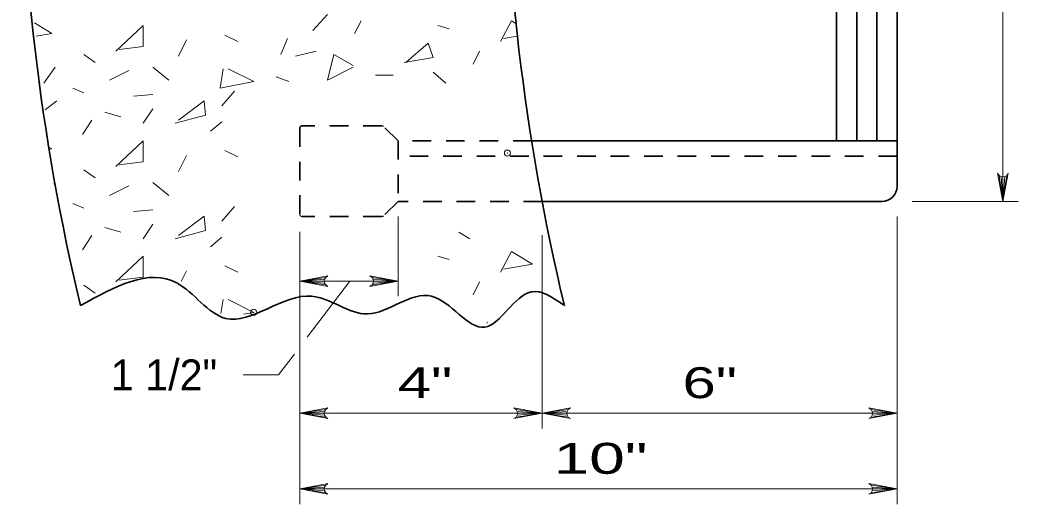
# Model space of a CAD drawing. Extents: x 16 to 133, y -56 to 112.
# Drawn here: x 22.21 to 55.21, y 65.71 to 81.71 of the extents above; entities that cross this region are included whole.
import ezdxf
from ezdxf.enums import TextEntityAlignment as Align

# ---------------------------------------------------------------- set-up
doc = ezdxf.new("R2010")
doc.units = 0
doc.header["$LTSCALE"] = 0.41
doc.header["$PDMODE"] = 32
doc.header["$PDSIZE"] = 0.205
doc.linetypes.add('SHORT_DASHED', pattern=[2.7, 1.5, -1.2])
for name, color, linetype, lineweight in [('1', 7, 'Continuous', 35), ('10', 7, 'Continuous', 13), ('13', 7, 'Continuous', 25), ('6', 7, 'Continuous', 13)]:
    doc.layers.add(name, color=color, linetype=linetype, lineweight=lineweight)

msp = doc.modelspace()

# ---------------------------------------------------------------- linework, layer by layer
at = {"layer": '1'}
for p, q in [((51.2132, 76.2094), (51.2132, 103.2094)), ((49.2132, 77.7094), (49.2132, 101.7094)), ((49.8798, 77.7094), (49.8798, 101.7094)), ((50.5465, 77.7094), (50.5465, 101.7094)), ((51.2132, 77.7094), (39.1307, 77.7094)), ((50.7132, 75.7094), (39.4787, 75.7094))]:
    msp.add_line(p, q, dxfattribs=at)
at = {"layer": '1', "linetype": 'SHORT_DASHED'}
for p, q in [((31.4632, 78.126), (31.4632, 75.2927)), ((34.1786, 78.2094), (31.5465, 78.2094)), ((34.7132, 77.7094), (34.2376, 78.185)), ((34.7132, 77.7094), (34.7132, 75.7094)), ((39.1307, 77.7094), (34.7132, 77.7094)), ((51.2132, 77.2094), (34.7132, 77.2094)), ((34.7132, 75.7094), (34.2376, 75.2338)), ((39.4787, 75.7094), (34.7132, 75.7094)), ((34.1786, 75.2094), (31.5465, 75.2094))]:
    msp.add_line(p, q, dxfattribs=at)
at = {"layer": '1'}
for centre, radius, start, end in [((95.4632, 89.267), 73.25, 166.58032, 193.41967), ((111.4632, 89.267), 73.25, 166.58032, 193.41967), ((50.7132, 76.2094), 0.5, 270, 0)]:
    msp.add_arc(centre, radius, start, end, dxfattribs=at)
at = {"layer": '1', "linetype": 'SHORT_DASHED'}
msp.add_arc((31.5465, 78.126), 0.0833, 90, 180, dxfattribs=at)
at = {"layer": '1'}
msp.add_spline([(24.2131, 72.267), (27.3964, 73.0185), (29.0086, 71.8453), (31.8666, 72.5785), (33.6986, 71.9919), (35.8238, 72.5785), (37.5826, 71.552), (39.1216, 72.7252), (40.2131, 72.267)], degree=3, dxfattribs=at)
at = {"layer": '10'}
for p, q in [((54.7132, 75.7094), (54.7132, 103.7094)), ((51.7132, 75.7094), (55.2132, 75.7094)), ((34.7132, 75.2094), (34.7132, 72.5756)), ((51.2132, 75.2094), (51.2132, 65.7094)), ((31.4632, 74.7094), (31.4632, 65.7094)), ((39.4787, 74.599), (39.4787, 68.2094)), ((34.7132, 73.0756), (31.4632, 73.0756)), ((31.7107, 71.222), (33.1186, 73.0756)), ((51.2132, 68.7094), (31.4632, 68.7094)), ((51.2132, 66.2094), (31.4632, 66.2094))]:
    msp.add_line(p, q, dxfattribs=at)
for points in [[(54.7132, 75.7094), (54.5384, 76.6414), (54.5882, 76.5696), (54.6507, 76.5326), (54.7132, 76.5219), (54.7757, 76.5326), (54.8382, 76.5696), (54.8879, 76.6414), (54.7132, 75.7094), (54.8382, 76.5696), (54.7757, 76.5326), (54.7132, 75.7094), (54.7132, 76.5219), (54.6507, 76.5326), (54.7132, 75.7094), (54.5882, 76.5696)], [(31.4632, 73.0756), (32.3952, 73.2503), (32.3234, 73.2006), (32.2864, 73.1381), (32.2757, 73.0756), (32.2864, 73.0131), (32.3234, 72.9506), (32.3952, 72.9008), (31.4632, 73.0756), (32.3234, 72.9506), (32.2864, 73.0131), (31.4632, 73.0756), (32.2757, 73.0756), (32.2864, 73.1381), (31.4632, 73.0756), (32.3234, 73.2006)], [(34.7132, 73.0756), (33.7811, 72.9008), (33.8529, 72.9506), (33.89, 73.0131), (33.9007, 73.0756), (33.89, 73.1381), (33.8529, 73.2006), (33.7811, 73.2503), (34.7132, 73.0756), (33.8529, 73.2006), (33.89, 73.1381), (34.7132, 73.0756), (33.9007, 73.0756), (33.89, 73.0131), (34.7132, 73.0756), (33.8529, 72.9506)], [(29.588, 69.9768), (30.7649, 69.9768), (31.287, 70.6642)], [(31.4632, 68.7094), (32.3952, 68.8841), (32.3234, 68.8344), (32.2864, 68.7719), (32.2757, 68.7094), (32.2864, 68.6469), (32.3234, 68.5844), (32.3952, 68.5346), (31.4632, 68.7094), (32.3234, 68.5844), (32.2864, 68.6469), (31.4632, 68.7094), (32.2757, 68.7094), (32.2864, 68.7719), (31.4632, 68.7094), (32.3234, 68.8344)], [(39.4787, 68.7094), (38.5467, 68.5346), (38.6185, 68.5844), (38.6555, 68.6469), (38.6662, 68.7094), (38.6555, 68.7719), (38.6185, 68.8344), (38.5467, 68.8841), (39.4787, 68.7094), (38.6185, 68.8344), (38.6555, 68.7719), (39.4787, 68.7094), (38.6662, 68.7094), (38.6555, 68.6469), (39.4787, 68.7094), (38.6185, 68.5844)], [(39.4787, 68.7094), (40.4108, 68.5346), (40.339, 68.5844), (40.302, 68.6469), (40.2912, 68.7094), (40.302, 68.7719), (40.339, 68.8344), (40.4108, 68.8841), (39.4787, 68.7094), (40.339, 68.8344), (40.302, 68.7719), (39.4787, 68.7094), (40.2912, 68.7094), (40.302, 68.6469), (39.4787, 68.7094), (40.339, 68.5844)], [(51.2132, 68.7094), (50.2811, 68.5346), (50.3529, 68.5844), (50.39, 68.6469), (50.4007, 68.7094), (50.39, 68.7719), (50.3529, 68.8344), (50.2811, 68.8841), (51.2132, 68.7094), (50.3529, 68.8344), (50.39, 68.7719), (51.2132, 68.7094), (50.4007, 68.7094), (50.39, 68.6469), (51.2132, 68.7094), (50.3529, 68.5844)], [(31.4632, 66.2094), (32.3952, 66.3841), (32.3234, 66.3344), (32.2864, 66.2719), (32.2757, 66.2094), (32.2864, 66.1469), (32.3234, 66.0844), (32.3952, 66.0346), (31.4632, 66.2094), (32.3234, 66.0844), (32.2864, 66.1469), (31.4632, 66.2094), (32.2757, 66.2094), (32.2864, 66.2719), (31.4632, 66.2094), (32.3234, 66.3344)], [(51.2132, 66.2094), (50.2811, 66.0346), (50.3529, 66.0844), (50.39, 66.1469), (50.4007, 66.2094), (50.39, 66.2719), (50.3529, 66.3344), (50.2811, 66.3841), (51.2132, 66.2094), (50.3529, 66.3344), (50.39, 66.2719), (51.2132, 66.2094), (50.4007, 66.2094), (50.39, 66.1469), (51.2132, 66.2094), (50.3529, 66.0844)]]:
    msp.add_lwpolyline(points, dxfattribs=at)
at = {"layer": '6'}
for p, q in [((32.3776, 81.8925), (31.901, 81.363)), ((33.4895, 81.6807), (33.2777, 81.2571)), ((36.0312, 81.5219), (36.4019, 81.416)), ((28.9887, 81.2042), (29.4123, 80.9924)), ((27.4531, 80.5158), (27.7178, 81.0453)), ((31.0538, 81.0983), (30.842, 80.5687)), ((38.6508, 81.173), (38.2022, 81.0983)), ((24.329, 80.5687), (24.6996, 80.304)), ((32.0069, 80.6747), (31.3185, 80.5158)), ((37.1961, 80.251), (37.4079, 80.6747)), ((23.3758, 80.1451), (23.0052, 79.6156)), ((25.8116, 80.0392), (25.1762, 79.7215)), ((26.6059, 80.1451), (27.1354, 79.7215)), ((33.9661, 79.8804), (34.5486, 79.8804)), ((35.8724, 79.9863), (36.296, 79.6156)), ((30.6831, 79.8274), (31.1067, 79.6686)), ((23.9583, 79.4568), (24.329, 79.2979)), ((25.9704, 79.192), (26.6059, 79.245)), ((28.8828, 78.8743), (29.3064, 79.3509)), ((23.4288, 79.0332), (23.0415, 78.7319)), ((25.0173, 78.6625), (25.5468, 78.5036)), ((26.2881, 78.2918), (26.6059, 78.7684)), ((24.5937, 78.3977), (24.276, 77.9212)), ((28.5121, 78.0271), (28.8828, 78.3448)), ((27.4531, 76.7033), (27.7178, 77.2328)), ((28.9887, 77.3917), (29.4123, 77.1799)), ((38.3313, 77.3073), (38.3313, 77.3073)), ((24.329, 76.7562), (24.6996, 76.4915)), ((23.3758, 76.3326), (23.3382, 76.2788)), ((26.6059, 76.3326), (27.1354, 75.909)), ((25.8116, 76.2267), (25.1762, 75.909)), ((23.9583, 75.6443), (24.329, 75.4854)), ((25.9704, 75.3795), (26.6059, 75.4325)), ((28.8828, 75.0618), (29.3064, 75.5384)), ((26.2881, 74.4793), (26.6059, 74.9559)), ((24.5937, 74.5852), (24.276, 74.1087)), ((25.0173, 74.85), (25.5468, 74.6911)), ((36.7196, 74.6911), (37.0902, 74.4793)), ((28.5121, 74.2146), (28.8828, 74.5323)), ((36.0312, 73.8969), (36.4019, 73.791)), ((27.5396, 73.0639), (27.7178, 73.4203)), ((28.9887, 73.5792), (29.4123, 73.3674)), ((24.329, 72.9437), (24.6996, 72.679)), ((37.1961, 72.626), (37.4079, 73.0497)), ((28.9357, 72.4672), (28.859, 72.007)), ((29.9411, 72.0439), (29.0946, 72.4672)), ((37.6487, 71.6839), (37.6727, 71.7259))]:
    msp.add_line(p, q, dxfattribs=at)
for points in [[(22.6992, 81.6083), (23.2699, 81.2571), (22.7513, 81.1707)], [(25.4939, 80.7276), (26.2881, 80.8335), (26.2881, 81.5219), (25.388, 80.6747)], [(38.0963, 80.9924), (38.467, 81.6807), (38.6137, 81.5904)], [(34.9192, 80.304), (35.8724, 80.4628), (35.7135, 80.9394), (34.9722, 80.304)], [(33.2248, 80.1451), (32.3776, 79.7215), (32.5894, 80.5687), (33.2248, 80.1981)], [(28.9357, 80.0922), (28.8298, 79.4568), (29.9418, 79.6686), (29.0946, 80.0922)], [(27.3472, 78.2918), (28.3532, 78.5566), (28.3003, 79.0332), (27.4531, 78.3977)], [(25.4939, 76.9151), (26.2881, 77.021), (26.2881, 77.7094), (25.388, 76.8622)], [(23.1887, 77.4946), (23.2699, 77.4446), (23.1961, 77.4323)], [(27.3472, 74.4793), (28.3532, 74.7441), (28.3003, 75.2207), (27.4531, 74.5852)], [(38.0963, 73.3674), (38.467, 74.0557), (39.1553, 73.6321), (38.2022, 73.4733)], [(25.4939, 73.1026), (26.2881, 73.2085), (26.2881, 73.8969), (25.388, 73.0497)], [(29.6119, 71.9807), (29.6119, 71.9807), (29.9389, 72.043)]]:
    msp.add_lwpolyline(points, dxfattribs=at)
at = {"layer": '6', "linetype": 'SHORT_DASHED'}
for centre, start, end in [((34.1787, 78.126), 45, 90), ((31.5465, 75.2927), 180, 270), ((34.1787, 75.2927), 270, 315)]:
    msp.add_arc(centre, 0.0833, start, end, dxfattribs=at)
at = {"layer": '6'}
for p in [(38.3313, 77.3073), (29.9389, 72.043)]:
    msp.add_point(p, dxfattribs=at)

# ---------------------------------------------------------------- texts
at = {"layer": '13'}
msp.add_text('1 1/2"', height=1.02, dxfattribs=at).set_placement((26.9751, 69.4668), align=Align.CENTER)
for s, width, p in [('4"', 1.45, (35.6059, 69.2094)), ('6"', 1.45, (45.0207, 69.2094)), ('10"', 1.55, (41.4098, 66.7094))]:
    msp.add_text(s, height=1.02, dxfattribs=dict(at, width=width)).set_placement(p, align=Align.CENTER)

doc.saveas('drawing.dxf')
